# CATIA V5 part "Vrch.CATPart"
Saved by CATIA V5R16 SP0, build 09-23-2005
Part number: Vrch
Bounding box of the stored display mesh (mm): x -60 to 60, y -60 to 60, z -110 to 20
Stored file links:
  H:\Dokumenty\CATIA\diskuze_catia\pruzina\Vrch.CATPart
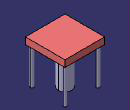
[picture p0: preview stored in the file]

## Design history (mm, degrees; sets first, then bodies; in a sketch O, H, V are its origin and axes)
Body1 (main body)
  Sketch1 on xy-plane, origin (0, 0, 0), H (1, 0, 0), V (0, 1, 0)
    line L1 (-60, 60) -> (60, 60)
    line L2 (60, 60) -> (60, -60)
    line L3 (60, -60) -> (-60, -60)
    line L4 (-60, -60) -> (-60, 60)
    distance L2 L4 = 120
    distance L3 L1 = 120
    horizontal: L1 H, L3 H
    vertical: L2 V, L4 V
    symmetry: L2 L4 V, L1 L3 H
  Pad1: profile Sketch1, direction (0, 0, 1), length 20
Body2
  Sketch2 on start face of Pad1, origin (0, 0, 0), H (1, 0, 0), V (0, -1, 0)
    circle A1 centre (50, 50) radius 5
    point P1 (50, 50)
    circle A2 centre (-50, 50) radius 5
    circle A3 centre (-50, -50) radius 5
    circle A4 centre (50, -50) radius 5
    circle A5 centre (0, 0) radius 20
    radius A1 = 5
    distance H P1 = 50
    distance V P1 = 50
    radius A5 = 20
    symmetry: A1 A2 V, A2 A3 H, A1 A4 H
  Pad2: profile Sketch2, direction (0, 0, -1), length 110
